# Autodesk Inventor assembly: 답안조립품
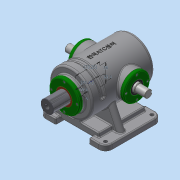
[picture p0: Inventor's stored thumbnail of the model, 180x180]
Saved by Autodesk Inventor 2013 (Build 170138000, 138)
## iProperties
Created: 2018-06
Part Number: 답안조립품
Document SubType Name: Assembly
Designer: Administrator
Author: Administrator
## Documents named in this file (13)
- C:\Users\Administrator\Desktop\380628V1012\답안조립품.iam
- C:\Users\Administrator\Desktop\380628V1012\본체.ipt
- C:\Users\Administrator\Desktop\380628V1012\가변스프링.ipt
- C:\Users\Administrator\Desktop\380628V1012\베어링 6205.ipt
- 베어링 6205.ipt
- C:\Users\Administrator\Desktop\380628V1012\볼트 M4.ipt
- C:\Users\Administrator\Desktop\380628V1012\부시.ipt
- C:\Users\Administrator\Desktop\380628V1012\슬라이드 커버.ipt
- C:\Users\Administrator\Desktop\380628V1012\슬라이드.ipt
- C:\Users\Administrator\Desktop\380628V1012\오일실.ipt
- 오일실.ipt
- C:\Users\Administrator\Desktop\380628V1012\축 커버.ipt
- C:\Users\Administrator\Desktop\380628V1012\편심축.ipt
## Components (1 placed, 1 different names)
1. 가변스프링:1
